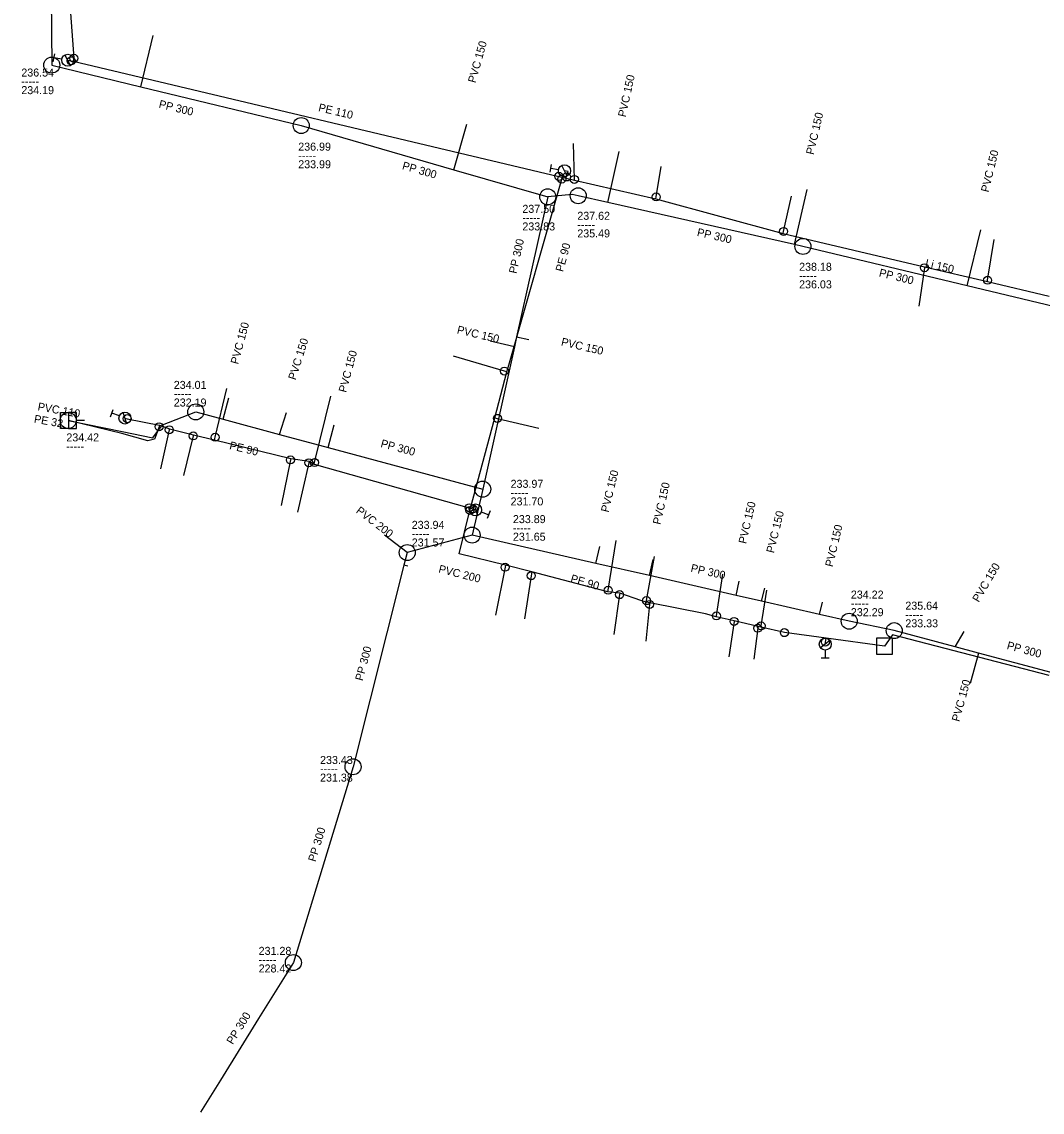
# Model space of a CAD drawing. Extents: x -771681 to -770485, y -1050143 to -1049574.
# Drawn here: x -771561 to -771433.4, y -1049940.2 to -1049804 of the extents above; entities that cross this region are included whole.
import ezdxf

# ---------------------------------------------------------------- set-up
doc = ezdxf.new("R2010")
doc.units = 0
doc.layers.add('Level 0', color=7, linetype='Continuous')

msp = doc.modelspace()

# ---------------------------------------------------------------- linework, layer by layer
at = {"layer": 'Level 0'}
for p, q in [((-771557.46, -1049777.92), (-771557.25, -1049809.4)), ((-771554.98, -1049801.78), (-771554.49, -1049808.55)), ((-771546.09, -1049812.1), (-771544.58, -1049805.7)), ((-771557.05, -1049808.98), (-771556.88, -1049807.99)), ((-771555.98, -1049808.66), (-771556.96, -1049808.49)), ((-771554.89, -1049809.45), (-771555.59, -1049808.13)), ((-771555.24, -1049808.79), (-771554.82, -1049808.87)), ((-771554.82, -1049808.87), (-771554.58, -1049808.92)), ((-771554.49, -1049808.55), (-771554.58, -1049808.92)), ((-771554.58, -1049808.92), (-771493.85, -1049823.3)), ((-771557.25, -1049809.4), (-771546.09, -1049812.1)), ((-771546.09, -1049812.1), (-771526.06, -1049816.95)), ((-771526.06, -1049816.95), (-771506.96, -1049822.47)), ((-771506.96, -1049822.47), (-771505.36, -1049816.8)), ((-771491.91, -1049823.69), (-771492.02, -1049819.19)), ((-771487.72, -1049826.55), (-771486.31, -1049820.2)), ((-771506.96, -1049822.47), (-771495.24, -1049825.86)), ((-771494.95, -1049822.79), (-771494.78, -1049821.8)), ((-771493.88, -1049822.47), (-771494.86, -1049822.3)), ((-771492.79, -1049823.26), (-771493.49, -1049821.94)), ((-771492.67, -1049822.7), (-771493.14, -1049822.6)), ((-771481.68, -1049825.87), (-771481.06, -1049822.07)), ((-771500.12, -1049846.91), (-771493.48, -1049823.65)), ((-771493.85, -1049823.3), (-771493.42, -1049823.4)), ((-771493.48, -1049823.65), (-771493.42, -1049823.4)), ((-771493.42, -1049823.4), (-771492.92, -1049823.52)), ((-771492.92, -1049823.52), (-771492.89, -1049823.38)), ((-771492.92, -1049823.52), (-771491.91, -1049823.79)), ((-771492.89, -1049823.38), (-771492.67, -1049822.7)), ((-771491.91, -1049823.79), (-771491.91, -1049823.69)), ((-771491.91, -1049823.79), (-771481.72, -1049826.13)), ((-771464.4, -1049831.81), (-771462.79, -1049824.94)), ((-771495.24, -1049825.86), (-771499.13, -1049843.34)), ((-771492.17, -1049825.56), (-771495.24, -1049825.86)), ((-771491.43, -1049825.72), (-771492.17, -1049825.56)), ((-771487.72, -1049826.55), (-771491.43, -1049825.72)), ((-771464.4, -1049831.81), (-771487.72, -1049826.55)), ((-771481.72, -1049826.13), (-771481.68, -1049825.87)), ((-771481.72, -1049826.13), (-771465.8, -1049830.43)), ((-771465.75, -1049830.18), (-771464.78, -1049825.78)), ((-771465.8, -1049830.43), (-771465.75, -1049830.18)), ((-771465.8, -1049830.43), (-771448.12, -1049834.59)), ((-771442.79, -1049836.98), (-771441.08, -1049829.98)), ((-771463.33, -1049832.05), (-771464.4, -1049831.81)), ((-771442.79, -1049836.98), (-771463.33, -1049832.05)), ((-771440.25, -1049836.29), (-771439.43, -1049831.18)), ((-771448.14, -1049834.72), (-771448.83, -1049839.54)), ((-771448.12, -1049834.59), (-771448.14, -1049834.72)), ((-771448.12, -1049834.59), (-771440.27, -1049836.44)), ((-771430.98, -1049839.82), (-771442.79, -1049836.98)), ((-771440.27, -1049836.44), (-771440.25, -1049836.29)), ((-771440.27, -1049836.44), (-771432.55, -1049838.26)), ((-771499.41, -1049844.59), (-771502.44, -1049843.88)), ((-771499.13, -1049843.34), (-771499.41, -1049844.59)), ((-771499.13, -1049843.34), (-771497.58, -1049843.7)), ((-771500.65, -1049847.64), (-771507.02, -1049845.75)), ((-771499.41, -1049844.59), (-771503.37, -1049862.39)), ((-771500.34, -1049847.73), (-771500.12, -1049846.91)), ((-771501.87, -1049853.46), (-771500.34, -1049847.73)), ((-771500.34, -1049847.73), (-771500.65, -1049847.64)), ((-771536.82, -1049855.9), (-771535.35, -1049849.83)), ((-771535.82, -1049853.66), (-771535.09, -1049850.96)), ((-771524.38, -1049859.06), (-771522.34, -1049850.78)), ((-771549.91, -1049853.37), (-771549.56, -1049852.43)), ((-771555.18, -1049853.82), (-771548.43, -1049855.17)), ((-771548.49, -1049855.45), (-771555.15, -1049853.8)), ((-771553.15, -1049853.8), (-771554.15, -1049853.8)), ((-771548.79, -1049853.24), (-771549.73, -1049852.9)), ((-771547.86, -1049854.21), (-771548.32, -1049852.79)), ((-771548.09, -1049853.5), (-771547.81, -1049853.58)), ((-771547.81, -1049853.58), (-771543.77, -1049854.41)), ((-771543.42, -1049854.36), (-771539.24, -1049852.74)), ((-771539.24, -1049852.74), (-771535.82, -1049853.66)), ((-771535.82, -1049853.66), (-771528.76, -1049855.55)), ((-771528.76, -1049855.55), (-771527.9, -1049852.83)), ((-771504.88, -1049864.75), (-771501.87, -1049853.46)), ((-771501.87, -1049853.46), (-771501.53, -1049853.54)), ((-771501.53, -1049853.54), (-771496.33, -1049854.75)), ((-771548.43, -1049855.17), (-771544.62, -1049855.96)), ((-771544.62, -1049855.96), (-771543.42, -1049854.36)), ((-771543.83, -1049854.59), (-771544.4, -1049856.16)), ((-771543.76, -1049854.4), (-771543.83, -1049854.59)), ((-771543.77, -1049854.41), (-771542.53, -1049854.87)), ((-771542.55, -1049854.97), (-771543.67, -1049859.84)), ((-771542.53, -1049854.87), (-771542.55, -1049854.97)), ((-771542.53, -1049854.87), (-771539.51, -1049855.59)), ((-771522.7, -1049857.19), (-771521.94, -1049854.35)), ((-771545.24, -1049856.33), (-771548.49, -1049855.45)), ((-771544.4, -1049856.16), (-771545.24, -1049856.33)), ((-771539.55, -1049855.74), (-771540.78, -1049860.69)), ((-771539.51, -1049855.59), (-771539.55, -1049855.74)), ((-771539.51, -1049855.59), (-771536.9, -1049856.23)), ((-771536.9, -1049856.23), (-771536.82, -1049855.9)), ((-771536.9, -1049856.23), (-771527.36, -1049858.54)), ((-771528.76, -1049855.55), (-771522.7, -1049857.19)), ((-771522.7, -1049857.19), (-771503.37, -1049862.39)), ((-771527.4, -1049858.74), (-771528.57, -1049864.42)), ((-771527.36, -1049858.54), (-771527.4, -1049858.74)), ((-771527.36, -1049858.54), (-771525.06, -1049858.9)), ((-771525.1, -1049859.09), (-771526.53, -1049865.27)), ((-771525.06, -1049858.9), (-771525.1, -1049859.09)), ((-771525.06, -1049858.9), (-771524.43, -1049859.25)), ((-771524.43, -1049859.25), (-771524.38, -1049859.06)), ((-771524.43, -1049859.25), (-771505.04, -1049864.71)), ((-771503.37, -1049862.39), (-771504.69, -1049868.13)), ((-771505.04, -1049864.71), (-771504.88, -1049864.75)), ((-771504.96, -1049865.05), (-771504.88, -1049864.75)), ((-771504.88, -1049864.75), (-771504.56, -1049864.85)), ((-771504.49, -1049864.27), (-771504.03, -1049865.69)), ((-771506.33, -1049870.47), (-771504.96, -1049865.05)), ((-771504.56, -1049864.85), (-771504.26, -1049864.98)), ((-771503.56, -1049865.24), (-771502.62, -1049865.58)), ((-771502.44, -1049865.11), (-771502.79, -1049866.05)), ((-771512.8, -1049870.31), (-771515.63, -1049868.14)), ((-771504.69, -1049868.13), (-771512.8, -1049870.31)), ((-771489.22, -1049871.66), (-771504.69, -1049868.13)), ((-771487.68, -1049875.02), (-771486.67, -1049868.81)), ((-771489.22, -1049871.66), (-771488.71, -1049869.56)), ((-771512.8, -1049870.31), (-771513.22, -1049871.89)), ((-771500.52, -1049871.9), (-771506.33, -1049870.47)), ((-771482.89, -1049876.32), (-771481.91, -1049870.81)), ((-771482.51, -1049873.19), (-771482.05, -1049871.19)), ((-771513.22, -1049871.89), (-771519.58, -1049897.08)), ((-771512.74, -1049872.01), (-771513.22, -1049871.89)), ((-771500.57, -1049872.15), (-771501.75, -1049878.15)), ((-771500.52, -1049871.9), (-771500.57, -1049872.15)), ((-771497.22, -1049872.71), (-771500.52, -1049871.9)), ((-771497.22, -1049872.71), (-771497.3, -1049873.2)), ((-771487.71, -1049875.22), (-771497.22, -1049872.71)), ((-771482.51, -1049873.19), (-771489.22, -1049871.66)), ((-771474.14, -1049878.23), (-771473.34, -1049873.01)), ((-771497.3, -1049873.2), (-771498.13, -1049878.61)), ((-771471.7, -1049875.66), (-771482.51, -1049873.19)), ((-771471.7, -1049875.66), (-771471.29, -1049873.9)), ((-771487.71, -1049875.22), (-771487.68, -1049875.02)), ((-771486.22, -1049875.37), (-771487.71, -1049875.22)), ((-771486.25, -1049875.57), (-771486.97, -1049880.57)), ((-771486.22, -1049875.37), (-771486.25, -1049875.57)), ((-771483.61, -1049876.32), (-771486.22, -1049875.37)), ((-771468.5, -1049876.39), (-771471.7, -1049875.66)), ((-771468.56, -1049879.47), (-771467.84, -1049875)), ((-771468.5, -1049876.39), (-771468.1, -1049874.77)), ((-771482.93, -1049876.52), (-771483.61, -1049876.32)), ((-771482.5, -1049876.8), (-771482.99, -1049881.38)), ((-771482.93, -1049876.52), (-771482.89, -1049876.32)), ((-771482.48, -1049876.6), (-771482.93, -1049876.52)), ((-771482.48, -1049876.6), (-771482.5, -1049876.8)), ((-771475.53, -1049877.98), (-771482.48, -1049876.6)), ((-771461.27, -1049878.04), (-771468.5, -1049876.39)), ((-771461.27, -1049878.04), (-771460.9, -1049876.49)), ((-771474.16, -1049878.33), (-771475.53, -1049877.98)), ((-771474.16, -1049878.33), (-771474.14, -1049878.23)), ((-771471.93, -1049878.83), (-771474.16, -1049878.33)), ((-771457.55, -1049878.89), (-771461.27, -1049878.04)), ((-771471.94, -1049878.91), (-771472.58, -1049883.33)), ((-771471.93, -1049878.83), (-771471.94, -1049878.91)), ((-771468.95, -1049879.54), (-771471.93, -1049878.83)), ((-771468.98, -1049879.76), (-771469.48, -1049883.62)), ((-771468.95, -1049879.54), (-771468.98, -1049879.76)), ((-771468.59, -1049879.63), (-771468.95, -1049879.54)), ((-771468.59, -1049879.63), (-771468.56, -1049879.47)), ((-771465.65, -1049880.32), (-771468.59, -1049879.63)), ((-771451.92, -1049880.07), (-771457.55, -1049878.89)), ((-771460.44, -1049881.02), (-771465.65, -1049880.32)), ((-771460.52, -1049881.5), (-771460.44, -1049881.02)), ((-771453.14, -1049882.01), (-771460.44, -1049881.02)), ((-771452.14, -1049881.01), (-771454.14, -1049881.01)), ((-771454.14, -1049881.01), (-771454.14, -1049883.01)), ((-771452.13, -1049880.59), (-771453.14, -1049882.01)), ((-771452.14, -1049883.01), (-771452.14, -1049881.01)), ((-771432.55, -1049885.68), (-771452.13, -1049880.59)), ((-771444.31, -1049882.1), (-771451.92, -1049880.07)), ((-771444.31, -1049882.1), (-771443.17, -1049880.17)), ((-771459.95, -1049881.29), (-771461.13, -1049882.21)), ((-771460.54, -1049881.75), (-771460.52, -1049881.5)), ((-771460.54, -1049882.5), (-771460.54, -1049883.5)), ((-771441.39, -1049882.88), (-771444.31, -1049882.1)), ((-771460.04, -1049883.5), (-771461.04, -1049883.5)), ((-771454.14, -1049883.01), (-771452.14, -1049883.01)), ((-771441.39, -1049882.88), (-771442.44, -1049886.67)), ((-771432.29, -1049885.31), (-771441.39, -1049882.88)), ((-771519.58, -1049897.08), (-771527.04, -1049921.55)), ((-771527.04, -1049921.55), (-771531.38, -1049928.53)), ((-771531.38, -1049928.53), (-771536.16, -1049936.24)), ((-771536.16, -1049936.24), (-771538.64, -1049940.24))]:
    msp.add_line(p, q, dxfattribs=at)
msp.add_lwpolyline([(-771555.15, -1049854.8), (-771556.15, -1049854.8), (-771556.15, -1049852.8), (-771555.15, -1049852.8)], dxfattribs=at)
msp.add_lwpolyline([(-771554.15, -1049854.8), (-771554.15, -1049852.8), (-771555.15, -1049852.8), (-771555.15, -1049854.8)], close=True, dxfattribs=at)
for centre, radius in [((-771557.25, -1049809.4), 1), ((-771555.24, -1049808.79), 0.75), ((-771554.82, -1049808.87), 0.5), ((-771554.49, -1049808.55), 0.5), ((-771526.06, -1049816.95), 1), ((-771493.14, -1049822.6), 0.75), ((-771493.85, -1049823.3), 0.5), ((-771493.48, -1049823.65), 0.5), ((-771492.89, -1049823.38), 0.5), ((-771491.91, -1049823.69), 0.5), ((-771495.24, -1049825.86), 1), ((-771491.43, -1049825.72), 1), ((-771481.68, -1049825.87), 0.5), ((-771465.75, -1049830.18), 0.5), ((-771463.33, -1049832.05), 1), ((-771448.14, -1049834.72), 0.5), ((-771440.25, -1049836.29), 0.5), ((-771500.65, -1049847.64), 0.5), ((-771539.24, -1049852.74), 1), ((-771555.18, -1049853.82), 1), ((-771548.09, -1049853.5), 0.75), ((-771547.81, -1049853.58), 0.5), ((-771501.53, -1049853.54), 0.5), ((-771543.83, -1049854.59), 0.5), ((-771542.55, -1049854.97), 0.5), ((-771539.55, -1049855.74), 0.5), ((-771536.82, -1049855.9), 0.5), ((-771527.4, -1049858.74), 0.5), ((-771525.1, -1049859.09), 0.5), ((-771524.38, -1049859.06), 0.5), ((-771503.37, -1049862.39), 1), ((-771505.04, -1049864.71), 0.5), ((-771504.96, -1049865.05), 0.5), ((-771504.56, -1049864.85), 0.5), ((-771504.26, -1049864.98), 0.75), ((-771504.69, -1049868.13), 1), ((-771512.8, -1049870.31), 1), ((-771500.57, -1049872.15), 0.5), ((-771497.3, -1049873.2), 0.5), ((-771487.68, -1049875.02), 0.5), ((-771486.25, -1049875.57), 0.5), ((-771482.89, -1049876.32), 0.5), ((-771482.5, -1049876.8), 0.5), ((-771474.14, -1049878.23), 0.5), ((-771471.94, -1049878.91), 0.5), ((-771457.55, -1049878.89), 1), ((-771468.98, -1049879.76), 0.5), ((-771468.56, -1049879.47), 0.5), ((-771465.65, -1049880.32), 0.5), ((-771451.92, -1049880.07), 1), ((-771460.54, -1049881.75), 0.75), ((-771460.52, -1049881.5), 0.5), ((-771519.58, -1049897.08), 1), ((-771527.04, -1049921.55), 1)]:
    msp.add_circle(centre, radius, dxfattribs=at)

# ---------------------------------------------------------------- texts
for s, rotation, p in [('PVC 150', 74.242, (-771504.28, -1049811.7)), ('PVC 150', 77.481, (-771485.5, -1049815.96)), ('PP 300', 346.389, (-771543.93, -1049814.71)), ('PE 110', 346.679, (-771523.98, -1049815.14)), ('PVC 150', 76.811, (-771462, -1049820.66)), ('PVC 150', 76.272, (-771440.13, -1049825.35)), ('PP 300', 343.868, (-771513.51, -1049822.39)), ('PP 300', 347.289, (-771476.64, -1049830.73)), ('PP 300', 77.374, (-771499.14, -1049835.52)), ('PE 90', 74.982, (-771493.32, -1049835.3)), ('PP 300', 346.479, (-771453.89, -1049835.79)), ('Li 150', 346.739, (-771448.12, -1049834.59)), ('PVC 150', 74.871, (-771533.95, -1049846.85)), ('PVC 150', 346.812, (-771506.65, -1049842.91)), ('PVC 150', 72.454, (-771526.76, -1049848.82)), ('PVC 150', 346.924, (-771493.63, -1049844.42)), ('PVC 150', 75.018, (-771520.44, -1049850.38)), ('PVC 110', 350, (-771559.06, -1049852.53)), ('PE 32', 350, (-771559.52, -1049854.07)), ('PE 90', 346.388, (-771535.1, -1049857.37)), ('PP 300', 345.013, (-771516.2, -1049857.11)), ('PVC 150', 76.35, (-771487.64, -1049865.35)), ('PVC 150', 77.047, (-771481.15, -1049866.88)), ('PVC 200', 322.52, (-771519.29, -1049865.26)), ('PVC 150', 76.887, (-771470.44, -1049869.28)), ('PVC 150', 76.13, (-771466.97, -1049870.44)), ('PVC 150', 76.574, (-771459.61, -1049872.17)), ('PVC 200', 345.964, (-771508.96, -1049872.79)), ('PP 300', 347.149, (-771477.43, -1049872.69)), ('PVC 150', 59.431, (-771441.36, -1049876.6)), ('PE 90', 343.61, (-771492.47, -1049873.97)), ('PP 300', 75.114, (-771518.37, -1049886.41)), ('PP 300', 345.044, (-771437.91, -1049882.35)), ('PVC 150', 74.515, (-771443.79, -1049891.51)), ('PP 300', 73.045, (-771524.27, -1049909.02)), ('PP 300', 58.202, (-771534.62, -1049931.86))]:
    msp.add_text(s, height=1, rotation=rotation, dxfattribs=at).set_placement(p)
for s, p in [('236.54', (-771561.05, -1049810.83)), ('-----', (-771561.05, -1049811.93)), ('234.19', (-771561.05, -1049813.03)), ('236.99', (-771526.43, -1049820.09)), ('-----', (-771526.43, -1049821.19)), ('233.99', (-771526.43, -1049822.29)), ('237.50', (-771498.41, -1049827.86)), ('237.62', (-771491.54, -1049828.73)), ('-----', (-771498.41, -1049828.96)), ('233.83', (-771498.41, -1049830.06)), ('-----', (-771491.54, -1049829.83)), ('235.49', (-771491.54, -1049830.93)), ('238.18', (-771463.81, -1049835.1)), ('-----', (-771463.81, -1049836.2)), ('236.03', (-771463.81, -1049837.3)), ('234.01', (-771541.99, -1049849.86)), ('-----', (-771541.99, -1049850.96)), ('232.19', (-771541.99, -1049852.06)), ('234.42', (-771555.42, -1049856.42)), ('-----', (-771555.42, -1049857.52)), ('233.97', (-771499.88, -1049862.22)), ('-----', (-771499.88, -1049863.32)), ('231.70', (-771499.88, -1049864.42)), ('233.89', (-771499.59, -1049866.63)), ('233.94', (-771512.24, -1049867.35)), ('-----', (-771499.59, -1049867.73)), ('-----', (-771512.24, -1049868.45)), ('231.57', (-771512.24, -1049869.55)), ('231.65', (-771499.59, -1049868.83)), ('234.22', (-771457.34, -1049876.06)), ('-----', (-771457.34, -1049877.16)), ('235.64', (-771450.53, -1049877.45)), ('232.29', (-771457.34, -1049878.26)), ('-----', (-771450.53, -1049878.55)), ('233.33', (-771450.53, -1049879.65)), ('233.43', (-771523.7, -1049896.73)), ('-----', (-771523.7, -1049897.83)), ('231.38', (-771523.7, -1049898.93)), ('231.28', (-771531.38, -1049920.58)), ('-----', (-771531.38, -1049921.68)), ('228.42', (-771531.38, -1049922.78))]:
    msp.add_text(s, height=1, dxfattribs=at).set_placement(p)

doc.saveas('drawing.dxf')
